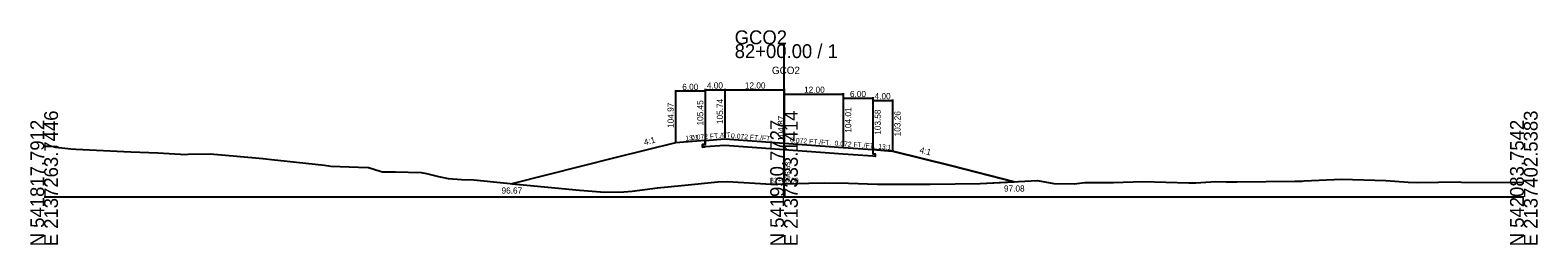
# Model space of a CAD drawing. Extents: x -14327 to 8886, y -10 to 39048.
# Drawn here: x 2997.2 to 3302.8, y 23990.3 to 24033.7 of the extents above; entities that cross this region are included whole.
import ezdxf

# ---------------------------------------------------------------- set-up
doc = ezdxf.new("R2010")
doc.units = 0
for name, color, linetype in [('Level 5', 7, 'Continuous'), ('Level 53', 7, 'Continuous'), ('Level 54', 7, 'Continuous'), ('Level 55', 7, 'Continuous'), ('Level 7', 7, 'Continuous'), ('RD_GPK_XS_Cell', 7, 'Continuous'), ('RD_XS_EwShp', 7, 'Continuous'), ('RD_XS_ExGround', 7, 'Continuous'), ('RD_XS_Pave', 7, 'Continuous'), ('RD_XS_TX_Baseline', 7, 'Continuous'), ('RD_XS_TX_Elev_EX', 7, 'Continuous'), ('RD_XS_TX_Elev_PR', 7, 'Continuous'), ('RD_XS_TX_Station', 7, 'Continuous')]:
    doc.layers.add(name, color=color, linetype=linetype)

msp = doc.modelspace()

# ---------------------------------------------------------------- linework, layer by layer
at = {"layer": 'Level 5'}
for p, q in [((3134, 24011.45), (3134, 24010.62)), ((3134, 24010.62), (3133.5, 24010.58)), ((3133.5, 24010.58), (3133.5, 24010.08)), ((3133.5, 24010.08), (3134, 24010.12)), ((3138, 24010.4), (3134, 24010.12)), ((3150, 24009.54), (3138, 24010.4)), ((3162, 24008.68), (3150, 24009.54)), ((3168, 24008.24), (3162, 24008.68)), ((3168, 24009.58), (3168, 24008.74)), ((3168, 24008.74), (3168.5, 24008.71)), ((3168.5, 24008.21), (3168, 24008.24)), ((3168.5, 24008.71), (3168.5, 24008.21))]:
    msp.add_line(p, q, dxfattribs=at)
at = {"layer": 'Level 54'}
for p, q in [((3128, 24021.6), (3128, 24011.17)), ((3134, 24021.4), (3128, 24021.4)), ((3134, 24021.89), (3134, 24011.65)), ((3134, 24021.69), (3138, 24021.69)), ((3134, 24021.6), (3134, 24011.65)), ((3138, 24021.89), (3138, 24011.94)), ((3138, 24021.69), (3150, 24021.69)), ((3150, 24021.89), (3150, 24011.07)), ((3150, 24021.02), (3150, 24011.07)), ((3150, 24020.82), (3162, 24020.82)), ((3162, 24021.02), (3162, 24010.21)), ((3162, 24020.16), (3162, 24010.21)), ((3162, 24019.96), (3168, 24019.96)), ((3168, 24020.16), (3168, 24009.78)), ((3168, 24019.73), (3168, 24009.78)), ((3168, 24019.53), (3172, 24019.53)), ((3172, 24019.73), (3172, 24009.46))]:
    msp.add_line(p, q, dxfattribs=at)
at = {"layer": 'Level 7'}
for p, q in [((3134, 24011.45), (3128, 24010.97)), ((3128, 24010.97), (3116, 24007.97)), ((3168, 24009.58), (3172, 24009.26)), ((3172, 24009.26), (3184, 24006.26)), ((3116, 24007.97), (3094.79, 24002.67)), ((3184, 24006.26), (3196.69, 24003.08))]:
    msp.add_line(p, q, dxfattribs=at)
at = {"layer": 'RD_GPK_XS_Cell'}
for p, q in [((3150, 24000), (3150, 24030.91)), ((3000, 24000), (3150, 24000)), ((3150, 24000), (3300, 24000))]:
    msp.add_line(p, q, dxfattribs=at)
at = {"layer": 'RD_XS_EwShp'}
msp.add_lwpolyline([(3094.79, 24002.67), (3097.83, 24002.37), (3108.56, 24001.36), (3113.67, 24000.99), (3117.5, 24001.04), (3119.23, 24001.14), (3124.33, 24001.84), (3129.19, 24002.34), (3136.61, 24003.07), (3138.45, 24003.11), (3147.44, 24002.55), (3150, 24002.63), (3155.06, 24002.8), (3158.14, 24002.84), (3163.08, 24002.77), (3168.9, 24002.58), (3174.78, 24002.56), (3179.66, 24002.58), (3189.75, 24002.72), (3196.69, 24003.08), (3184, 24006.26), (3172, 24009.26), (3168, 24009.58), (3168, 24008.74), (3168.5, 24008.71), (3168.5, 24008.21), (3168, 24008.24), (3162, 24008.68), (3150, 24009.54), (3138, 24010.4), (3134, 24010.12), (3133.5, 24010.08), (3133.5, 24010.58), (3134, 24010.62), (3134, 24011.45), (3128, 24010.97), (3116, 24007.97)], close=True, dxfattribs=at)
at = {"layer": 'RD_XS_ExGround'}
for p, q in [((3000, 24010.27), (3000.86, 24010.29)), ((3000.86, 24010.29), (3001.54, 24010.3)), ((3001.54, 24010.3), (3002.53, 24010.19)), ((3002.53, 24010.19), (3002.98, 24009.98)), ((3002.98, 24009.98), (3005.41, 24009.75)), ((3005.41, 24009.75), (3006.4, 24009.65)), ((3006.4, 24009.65), (3017.54, 24009.14)), ((3017.54, 24009.14), (3023.07, 24008.91)), ((3023.07, 24008.91), (3027.63, 24008.63)), ((3027.63, 24008.63), (3028.09, 24008.61)), ((3028.09, 24008.61), (3029.21, 24008.63)), ((3029.21, 24008.63), (3033.63, 24008.74)), ((3033.63, 24008.74), (3039.05, 24008.25)), ((3039.05, 24008.25), (3044.33, 24007.78)), ((3044.33, 24007.78), (3046.67, 24007.51)), ((3046.67, 24007.51), (3047.39, 24007.46)), ((3047.39, 24007.46), (3056.81, 24006.44)), ((3056.81, 24006.44), (3058.14, 24006.23)), ((3058.14, 24006.23), (3063.71, 24006.02)), ((3063.71, 24006.02), (3065.73, 24005.93)), ((3065.73, 24005.93), (3068.13, 24005.22)), ((3068.13, 24005.22), (3068.57, 24005.08)), ((3068.57, 24005.08), (3071.24, 24005.05)), ((3071.24, 24005.05), (3076.43, 24004.93)), ((3076.43, 24004.93), (3077.55, 24004.72)), ((3077.55, 24004.72), (3079.97, 24004.1)), ((3079.97, 24004.1), (3081.88, 24003.7)), ((3081.88, 24003.7), (3084.63, 24003.54)), ((3084.63, 24003.54), (3087.13, 24003.48)), ((3087.13, 24003.48), (3093.1, 24002.83)), ((3093.1, 24002.83), (3097.83, 24002.37)), ((3097.83, 24002.37), (3108.56, 24001.36)), ((3124.33, 24001.84), (3129.19, 24002.34)), ((3129.19, 24002.34), (3136.61, 24003.07)), ((3136.61, 24003.07), (3138.45, 24003.11)), ((3138.45, 24003.11), (3147.44, 24002.55)), ((3147.44, 24002.55), (3150, 24002.63)), ((3150, 24002.63), (3155.06, 24002.8)), ((3155.06, 24002.8), (3158.14, 24002.84)), ((3158.14, 24002.84), (3163.08, 24002.77)), ((3163.08, 24002.77), (3168.9, 24002.58)), ((3168.9, 24002.58), (3174.78, 24002.56)), ((3174.78, 24002.56), (3179.66, 24002.58)), ((3179.66, 24002.58), (3189.75, 24002.72)), ((3189.75, 24002.72), (3201.37, 24003.33)), ((3201.37, 24003.33), (3204.73, 24002.72)), ((3204.73, 24002.72), (3208.82, 24002.67)), ((3208.82, 24002.67), (3211.01, 24002.91)), ((3211.01, 24002.91), (3211.95, 24002.93)), ((3211.95, 24002.93), (3216.8, 24002.91)), ((3216.8, 24002.91), (3222.72, 24003.11)), ((3222.72, 24003.11), (3232.11, 24002.84)), ((3232.11, 24002.84), (3233.48, 24002.83)), ((3233.48, 24002.83), (3237.52, 24003.15)), ((3237.52, 24003.15), (3239.67, 24003.05)), ((3239.67, 24003.05), (3240.92, 24003.06)), ((3240.92, 24003.06), (3241.22, 24003.04)), ((3241.22, 24003.04), (3241.9, 24003.06)), ((3241.9, 24003.06), (3253.59, 24003.19)), ((3253.59, 24003.19), (3255.07, 24003.21)), ((3255.07, 24003.21), (3255.43, 24003.23)), ((3255.43, 24003.23), (3263, 24003.6)), ((3263, 24003.6), (3272.05, 24003.32)), ((3272.05, 24003.32), (3276.53, 24002.96)), ((3276.53, 24002.96), (3278.5, 24002.95)), ((3278.5, 24002.95), (3286.88, 24003.02)), ((3286.88, 24003.02), (3287.36, 24003.01)), ((3287.36, 24003.01), (3300, 24002.9)), ((3108.56, 24001.36), (3113.67, 24000.99)), ((3113.67, 24000.99), (3117.5, 24001.04)), ((3117.5, 24001.04), (3119.23, 24001.14)), ((3119.23, 24001.14), (3124.33, 24001.84))]:
    msp.add_line(p, q, dxfattribs=at)
at = {"layer": 'RD_XS_Pave'}
for p, q in [((3134, 24011.45), (3138, 24011.74)), ((3138, 24011.74), (3150, 24010.87)), ((3150, 24010.87), (3162, 24010.01)), ((3162, 24010.01), (3168, 24009.58))]:
    msp.add_line(p, q, dxfattribs=at)

# ---------------------------------------------------------------- texts
at = {"layer": 'Level 53'}
for s, rotation, p in [('104.97', 90, (3127.63, 24013.97)), ('105.45', 90, (3133.63, 24014.45)), ('105.74', 90, (3137.63, 24014.74)), ('104.01', 90, (3163.63, 24013.01)), ('103.58', 90, (3169.62, 24012.58)), ('103.26', 90, (3173.62, 24012.26)), ('4:1', 14.0362, (3121.76, 24010.44)), ('4:1', 345.9638, (3177.39, 24008.94))]:
    msp.add_text(s, height=1.25, rotation=rotation, dxfattribs=at).set_placement(p)
for s, p in [('97.08', (3194.6, 24001.08)), ('96.67', (3092.73, 24000.67))]:
    msp.add_text(s, height=1.25, dxfattribs=at).set_placement(p)
at = {"layer": 'Level 54'}
for s, p in [('6.00', (3129.37, 24021.65)), ('4.00', (3134.37, 24021.94)), ('12.00', (3142.07, 24021.94)), ('12.00', (3154.07, 24021.07)), ('6.00', (3163.37, 24020.21)), ('4.00', (3168.37, 24019.78))]:
    msp.add_text(s, height=1.25, dxfattribs=at).set_placement(p)
at = {"layer": 'Level 55'}
for s, rotation, p in [('13:1', 4.5739, (3130.03, 24011.38)), ('0.072 FT./FT.', 4.1182, (3131.18, 24011.5)), ('0.072 FT./FT.', 355.8818, (3139.22, 24011.9)), ('0.072 FT./FT.', 355.8818, (3151.22, 24011.04)), ('0.072 FT./FT.', 355.8818, (3160.22, 24010.39)), ('13:1', 355.4261, (3169.07, 24009.74))]:
    msp.add_text(s, height=1, rotation=rotation, dxfattribs=at).set_placement(p)
at = {"layer": 'RD_GPK_XS_Cell'}
for s, p in [('GCO2', (3140, 24030.91)), ('82+00.00 / 1', (3140, 24028.11))]:
    msp.add_text(s, height=2.8, dxfattribs=at).set_placement(p)
for s, p in [('N 541817.7912', (3000, 23990)), ('E 2137263.7446', (3002.8, 23990)), ('N 541950.7727', (3150, 23990)), ('E 2137333.1414', (3152.8, 23990)), ('N 542083.7542', (3300, 23990)), ('E 2137402.5383', (3302.8, 23990))]:
    msp.add_text(s, height=2.8, rotation=90, dxfattribs=at).set_placement(p)
at = {"layer": 'RD_XS_TX_Baseline'}
msp.add_text('GCO2', height=1.5, dxfattribs=at).set_placement((3147.55, 24024.87))
at = {"layer": 'RD_XS_TX_Elev_EX'}
msp.add_text('96.63', height=1, rotation=90, dxfattribs=at).set_placement((3151.25, 24003.63))
at = {"layer": 'RD_XS_TX_Elev_PR'}
msp.add_text(' 104.87', height=1.25, rotation=90, dxfattribs=at).set_placement((3150, 24010.87))
at = {"layer": 'RD_XS_TX_Station'}
msp.add_text('82+00.00', height=1, dxfattribs=at).set_placement((3147.16, 24002.87))

doc.saveas('drawing.dxf')
